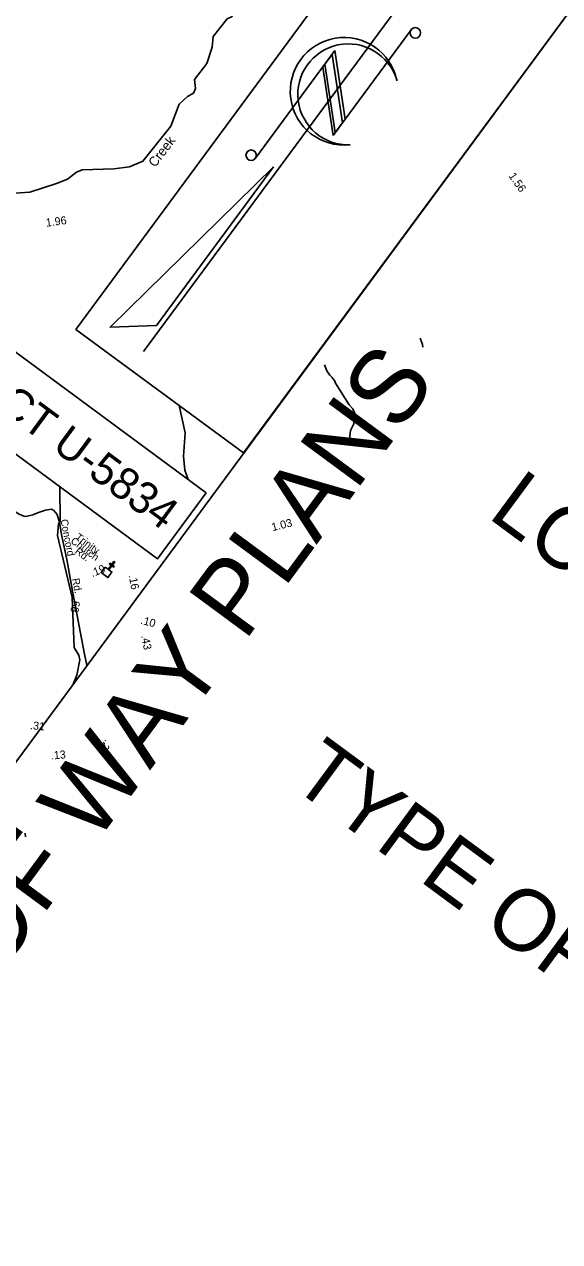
# Model space of a CAD drawing. Extents: x 945666 to 965748, y 644452 to 663300.
# Drawn here: x 955557 to 956642, y 656118 to 658587 of the extents above; entities that cross this region are included whole.
import ezdxf

# ---------------------------------------------------------------- set-up
doc = ezdxf.new("R2010")
doc.units = 0
for name, color, linetype in [('Exist Cultural Church CELL', 7, 'Continuous'), ('Exist Hydrographic Creek Single Shore', 7, 'Continuous'), ('Exist Hydrographic Misc Water Feature', 7, 'Continuous'), ('Exist Road Secondary Mileage Tenths English Label', 7, 'Continuous'), ('Exist Road Secondary Type 51 Attributed', 7, 'Continuous'), ('Exist Road Secondary Type 51 Label', 7, 'Continuous'), ('Old_Level_1', 7, 'Continuous'), ('Old_Level_48', 7, 'Continuous'), ('Prop EOT', 7, 'Continuous'), ('Prop Paved Shoulder', 7, 'Continuous'), ('Sheet North Arrow CELL', 7, 'Continuous'), ('Sheet Sticker Preliminary CELL', 7, 'Continuous'), ('Sheet Title CELL', 7, 'Continuous')]:
    doc.layers.add(name, color=color, linetype=linetype)

msp = doc.modelspace()

# ---------------------------------------------------------------- linework, layer by layer
at = {"layer": 'Exist Cultural Church CELL'}
msp.add_lwpolyline([(955720.7, 657485.7), (955726.7, 657481.4), (955732.5, 657489.3), (955729.2, 657491.8), (955730.4, 657493.5), (955733.8, 657491), (955738.4, 657497.3), (955740.1, 657496.1), (955735.4, 657489.8), (955738.8, 657487.3), (955737.6, 657485.6), (955734.2, 657488.1), (955728.3, 657480.1), (955734.4, 657475.7), (955726.1, 657464.5), (955712.5, 657474.6)], close=True, dxfattribs=at)
at = {"layer": 'Exist Hydrographic Creek Single Shore'}
for points in [[(955662.4, 658287.1), (955673.9, 658291.2), (955738, 658293.6), (955770, 658297.4), (955797.1, 658308.9), (955853.7, 658380.4), (955870.9, 658424.7), (955887.5, 658440.4), (955899.7, 658447.2), (955904.1, 658456.2), (955902, 658474.4), (955926.8, 658507.5), (955937.5, 658540.2), (955939.7, 658562.1), (955968, 658597.9), (955976.8, 658601.9), (956001.7, 658633.3), (956006.1, 658661.6), (956021.6, 658693.3), (956051.3, 658729), (956057.4, 658757.7), (956064.1, 658785.3), (956061.1, 658804.3), (956061.5, 658808.1)], [(955236.5, 658150), (955240.3, 658152), (955260.7, 658169.1), (955295.4, 658169.3), (955307.2, 658173.7), (955343.4, 658200.2), (955401.2, 658234.8), (955426.9, 658244.6), (955462.8, 658242.8), (955471.2, 658248.2), (955500.7, 658252.3), (955516.6, 658242.8), (955567.8, 658246.4), (955621.9, 658264), (955644.2, 658272.6), (955662.4, 658287.1)], [(955888.8, 657663.7), (955882, 657682.3), (955879.5, 657710.5), (955882.6, 657758.1), (955870.4, 657813.6)], [(955655.5, 657248.5), (955662.9, 657266.3), (955669.4, 657297.3), (955667.4, 657306.9), (955657.9, 657322.8), (955653.7, 657423.9), (955623.9, 657550.1), (955625.7, 657573.4), (955629.2, 657577.7), (955628.4, 657649.1)]]:
    msp.add_lwpolyline(points, dxfattribs=at)
at = {"layer": 'Exist Hydrographic Misc Water Feature'}
msp.add_line((955559, 656938.6), (955558.2, 656945.9), dxfattribs=at)
for points in [[(956359.4, 657950.3), (956363.7, 657936.9), (956364.8, 657931.9)], [(956165.2, 657896.1), (956170.1, 657883.9), (956175.9, 657875.3), (956180.7, 657870.5), (956186, 657863), (956187.4, 657858.9), (956215.6, 657815), (956222.9, 657806.6), (956226.9, 657797.5), (956226.9, 657784.9), (956223.8, 657774.7), (956218.2, 657762.6), (956216.8, 657750.8), (956217.8, 657732.6)]]:
    msp.add_lwpolyline(points, dxfattribs=at)
at = {"layer": 'Exist Road Secondary Type 51 Attributed'}
for points in [[(955514.1, 657613.9), (955524.5, 657607.4), (955537.4, 657598.3), (955546.3, 657593), (955555.4, 657588.9), (955559.7, 657588.4), (955573.8, 657591.7), (955585.4, 657596.3), (955599.8, 657601.5), (955611.6, 657603.2)], [(955611.6, 657603.2), (955616.8, 657600.2), (955623.2, 657592.6), (955628, 657576.2), (955632.6, 657548.5), (955642.6, 657501)], [(955642.6, 657501), (955655.3, 657433.6), (955678.9, 657309.3), (955683.7, 657286.6)]]:
    msp.add_lwpolyline(points, dxfattribs=at)
at = {"layer": 'Old_Level_1'}
for points in [[(953667.4, 661172.9), (956829.7, 658840.6), (955088.6, 656479.8), (951926.2, 658812.1)], [(956489.9, 659091.3), (956829.7, 658840.6), (956001.2, 657717.2), (955661.3, 657967.8)]]:
    msp.add_lwpolyline(points, close=True, dxfattribs=at)
at = {"layer": 'Prop EOT'}
msp.add_lwpolyline([(955925.6, 657636.6), (955029.8, 658297.3), (954931, 658163.4), (955826.8, 657502.7)], close=True, dxfattribs=at)
at = {"layer": 'Sheet North Arrow CELL'}
for p, q in [((955798.5, 657922.7), (956570.1, 658968.9)), ((956341, 658575.8), (956182.7, 658361)), ((956186.4, 658533.5), (956025.4, 658315.2)), ((956207.4, 658394.5), (956186.4, 658533.5)), ((956180.5, 658525.6), (956166.1, 658506)), ((956201.5, 658386.6), (956180.5, 658525.6)), ((956182.7, 658361), (956161.7, 658500)), ((956187.1, 658367), (956166.1, 658506)), ((956166.1, 658506), (956187.1, 658367)), ((956311.6, 658473.9), (956312.2, 658472.3)), ((956187.1, 658367), (956201.5, 658386.6))]:
    msp.add_line(p, q, dxfattribs=at)
msp.add_lwpolyline([(956061.8, 658297.6), (955730.7, 657972.7), (955824.4, 657975.7)], close=True, dxfattribs=at)
for centre in [(956349.4, 658569.3), (956016.6, 658321.2)]:
    msp.add_circle(centre, 10.6, dxfattribs=at)
for centre, radius, start, end in [((956205.1, 658450.7), 109.2, 11.4309, 275.9849), ((956213.6, 658444.5), 102.4, 16.6859, 272.2196)]:
    msp.add_arc(centre, radius, start, end, dxfattribs=at)

# ---------------------------------------------------------------- texts
at = {"layer": 'Exist Road Secondary Mileage Tenths English Label'}
for s, rotation, p in [('1.56', 305.0524, (956537.8, 658279)), ('1.96', 7.5341, (955601.4, 658176.1)), ('1.03', 14.029, (956060.1, 657558.4)), ('.19', 21.843, (955694.6, 657465.2)), ('.16', 281.0805, (955768.1, 657468.6)), ('.68', 260.1477, (955655.2, 657424.5)), ('.10', 344.9654, (955791.2, 657371.1)), ('.43', 281.1076, (955793.5, 657346.4)), ('.31', 354.595, (955567.8, 657157.1)), ('.23', 234.613, (955721.7, 657137.2))]:
    msp.add_text(s, height=16.24, rotation=rotation, dxfattribs=at).set_placement(p)
at = {"layer": 'Exist Road Secondary Type 51 Label'}
for s, rotation, p in [('Concord', 281.0805, (955629.9, 657581.4)), ('Church', 323.5908, (955649.3, 657535.9)), ('Trinity', 323.5908, (955658.6, 657543.6)), ('Rd.', 323.5908, (955657.9, 657515.1)), ('Rd.', 281.047, (955653.3, 657461.8))]:
    msp.add_text(s, height=15, rotation=rotation, dxfattribs=at).set_placement(p)
at = {"layer": 'Old_Level_48'}
msp.add_text('END TIP PROJECT U-5834', height=64.231, rotation=323.5908, dxfattribs=at).set_placement((954976.9, 658193.2))
at = {"layer": 'Prop Paved Shoulder'}
msp.add_text('Creek', height=19.49, rotation=52.5472, dxfattribs=at).set_placement((955821.9, 658295.3))
at = {"layer": 'Sheet Sticker Preliminary CELL'}
msp.add_text('.13', height=16.24, rotation=5.19, dxfattribs=at).set_placement((955611.3, 657095.3))
at = {"layer": 'Sheet Title CELL'}
for s, height, rotation, p in [('RIGHT OF WAY PLANS', 150, 53.5908, (955097, 656104.3)), ('LOCATION: ', 125, 323.5908, (956493.8, 657587.7)), ('TYPE OF WORK:', 125.001, 323.5908, (956093.1, 657044.4))]:
    msp.add_text(s, height=height, rotation=rotation, dxfattribs=at).set_placement(p)

doc.saveas('drawing.dxf')
